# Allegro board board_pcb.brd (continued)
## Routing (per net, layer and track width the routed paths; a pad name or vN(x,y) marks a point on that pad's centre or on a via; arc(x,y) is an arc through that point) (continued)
LCD_G1: length 121.1
  TOP w0.152: J1.14 113.1,102.62 117.02,98.7 117.02,97.94 117.53,97.43 117.53,97 117.81,96.72 117.81,96.5 117.62,96.31 117.62,96.1 117.84,95.88 118.05,95.88 118.24,96.07 118.46,96.07 118.87,95.66 119.2,95.66 119.74,96.19 120.22,96.19 120.52,95.89 120.52,94.72 120.29,94.49 J2.14 ; U1.N13 v2(55.67,66.85)
  BOTTOM w0.152: J2.14 119,92.93 119.15,92.77 119.48,92.77 119.63,92.62 119.63,92.32 119.48,92.16 119.15,92.16 119,92.01 119,91.71 119.15,91.55 119.48,91.55 119.63,91.4 119.63,91.1 119.48,90.94 119.15,90.94 119,90.79 119,90.04 118.85,89.89 118.4,89.89 118.25,90.04 118.25,92.68 118.1,92.84 117.79,92.84 117.64,92.68 117.64,90.04 117.49,89.89 117.18,89.89 117.03,90.04 117.03,92.02 116.88,92.18 116.57,92.18 116.42,92.02 116.42,90.04 116.27,89.89 115.96,89.89 115.81,90.04 115.81,91.01 115.66,91.16 115.35,91.16 115.2,91.01 115.2,90.04 114.43,89.27 92.09,89.27 90.04,87.22 90.04,86.45 89.89,86.3 89.31,86.3 89.15,86.15 89.15,85.85 89.31,85.69 89.89,85.69 90.04,85.54 90.04,84.71 89.75,84.42 89.54,84.42 88.67,85.28 88.46,85.28 88.24,85.07 88.24,84.85 89.11,83.99 89.11,83.77 88.89,83.56 88.67,83.56 87.81,84.42 87.6,84.42 87.38,84.2 87.38,83.99 88.24,83.12 88.24,82.91 87.76,82.42 86.87,82.42 86.11,81.66 86.11,80.64 85.93,80.47 85.71,80.47 85.48,80.7 85.27,80.7 85.05,80.48 85.05,80.26 85.28,80.03 85.28,79.82 85.06,79.6 84.85,79.6 84.62,79.83 84.4,79.83 84.19,79.62 84.19,79.4 84.42,79.17 84.42,78.96 84.2,78.74 83.99,78.74 83.76,78.97 83.54,78.97 83.33,78.75 83.33,78.54 83.56,78.31 83.56,78.09 80.61,75.14 62.44,75.14 61.49,74.19 61.49,72.75 60.96,72.21 59.26,72.21 57.66,70.61 57.66,70.23 56.07,68.64 56.07,67.25 v2(55.67,66.85)
LCD_G2: length 121.3
  TOP w0.152: U1.M14 v2(54.87,67.65) ; 116.46,97.03 115.54,97.03 115.39,97.18 115.39,97.64 115.82,98.07 116.51,98.07 116.66,98.22 116.66,98.55 116.18,99.04 115.96,99.04 115.54,98.62 115.33,98.62 115.11,98.83 115.11,99.05 115.53,99.47 115.53,99.68 115.31,99.9 115.1,99.9 114.68,99.48 114.46,99.48 114.25,99.7 114.25,99.91 114.67,100.33 114.67,100.55 114.45,100.76 114.24,100.76 113.82,100.34 113.6,100.34 113.39,100.56 113.39,100.78 113.8,101.19 113.8,101.41 113.59,101.63 113.37,101.63 112.95,101.21 112.74,101.21 112.52,101.42 112.52,101.64 112.94,102.06 112.94,102.27 112.61,102.61 J1.15
  BOTTOM w0.152: v2(54.87,67.65) U1.M14 53.82,67.25 53.67,67.4 53.67,68.71 53.11,69.27 53.11,70.38 52.02,71.48 52.02,73.2 55.27,76.45 58.42,76.45 58.8,76.83 73.86,76.83 74.28,77.25 74.28,77.47 73.51,78.24 73.51,78.46 73.72,78.68 73.94,78.68 74.71,77.9 74.93,77.9 75.15,78.12 75.15,78.33 74.37,79.11 74.37,79.32 74.59,79.54 74.8,79.54 75.58,78.76 75.79,78.76 76.01,78.98 76.01,79.2 75.23,79.97 75.23,80.19 75.45,80.4 75.66,80.4 76.44,79.63 76.65,79.63 76.87,79.84 76.87,80.06 76.1,80.83 76.1,81.05 76.31,81.26 76.53,81.26 77.3,80.49 77.52,80.49 77.73,80.7 77.73,80.92 76.96,81.7 76.96,81.91 77.17,82.13 77.39,82.13 78.16,81.35 78.38,81.35 78.59,81.56 78.59,81.86 78.36,82.09 78.36,82.4 78.73,82.77 78.73,82.98 78.5,83.21 78.5,83.43 78.72,83.64 78.93,83.64 79.16,83.41 79.38,83.41 79.59,83.63 79.59,83.84 79.36,84.07 79.36,84.29 79.58,84.51 79.79,84.51 80.02,84.28 80.24,84.28 80.45,84.49 80.45,84.71 80.22,84.94 80.22,85.15 80.44,85.37 80.66,85.37 80.88,85.14 81.1,85.14 81.32,85.35 81.32,85.57 81.09,85.8 81.09,86.01 81.3,86.23 81.52,86.23 81.75,86 81.96,86 82.18,86.22 82.18,86.43 81.95,86.66 81.95,86.88 82.17,87.09 82.38,87.09 82.61,86.86 82.83,86.86 83.07,87.11 83.07,87.33 82.7,87.7 82.7,87.91 82.92,88.13 83.13,88.13 83.5,87.76 83.72,87.76 83.94,87.97 83.94,88.19 83.57,88.56 83.57,88.77 83.78,88.99 84,88.99 84.37,88.62 84.58,88.62 84.8,88.84 84.8,89.05 84.43,89.42 84.43,89.64 84.64,89.85 84.86,89.85 85.23,89.48 85.44,89.48 86.87,90.91 112.19,90.91 115.32,94.03 115.32,95.89 116.46,97.03
LCD_G3: length 121.2
  TOP w0.152: U1.L14 v2(54.07,67.65) ; 116.46,94.49 116.92,94.03 117.7,94.03 117.86,94.18 117.86,95.33 117.65,95.53 117.27,95.53 117.11,95.68 117.11,95.83 116.96,95.99 116.66,95.99 116.51,95.83 116.51,95.68 116.35,95.53 115.9,95.53 115.77,95.66 115.77,95.87 115.84,95.94 115.84,96.15 115.62,96.37 115.4,96.37 115.34,96.31 115.12,96.31 114.96,96.47 114.96,97.74 115.21,97.99 115.21,98.22 112.17,101.27 112.17,101.8 112.41,102.05 112.41,102.27 112.1,102.58 J1.16
  BOTTOM w0.152: 116.46,94.49 112.48,90.51 89.56,90.51 87.93,88.88 87.72,88.88 86.82,89.78 86.61,89.78 86.39,89.56 86.39,89.35 87.29,88.45 87.29,88.24 87.07,88.02 86.85,88.02 85.96,88.92 85.74,88.92 85.53,88.7 85.53,88.49 86.42,87.59 86.42,87.37 86.21,87.16 85.99,87.16 85.1,88.05 84.88,88.05 84.66,87.84 84.66,87.62 85.56,86.73 85.56,86.51 85.34,86.3 85.13,86.3 84.23,87.19 84.02,87.19 83.8,86.98 83.8,86.76 84.7,85.86 84.7,85.65 84.48,85.43 84.27,85.43 83.37,86.33 83.16,86.33 82.94,86.11 82.94,85.9 83.84,85 83.84,84.79 83.62,84.57 83.4,84.57 82.51,85.47 82.29,85.47 82.08,85.25 82.08,85.04 82.97,84.14 82.97,83.92 82.76,83.71 82.54,83.71 81.65,84.6 81.43,84.6 81.21,84.39 81.21,84.17 82.11,83.28 82.11,83.06 81.89,82.85 81.68,82.85 80.78,83.74 80.57,83.74 80.35,83.53 80.35,83.31 81.25,82.41 81.25,82.2 81.03,81.98 80.82,81.98 79.92,82.88 79.7,82.88 79.49,82.66 79.49,82.45 80.39,81.55 80.39,81.34 80.14,81.09 79.78,81.09 79.46,81.41 79.25,81.41 74.22,76.38 58.98,76.38 58.55,75.95 55.35,75.95 52.45,73.05 52.45,71.63 53.53,70.55 53.53,69.65 54.47,68.71 54.47,68.05 v2(54.07,67.65)
LCD_G4: length 121.4
  TOP w0.152: J2.17 113.92,96.19 113.77,96.04 113.03,96.04 112.84,96.23 112.84,97.9 113,98.07 114.29,98.07 114.44,98.22 114.44,98.44 113.56,99.32 113.34,99.32 112.74,98.72 112.53,98.72 112.31,98.94 112.31,99.15 112.91,99.75 112.91,99.97 112.69,100.18 112.48,100.18 111.91,99.61 111.69,99.61 111.48,99.83 111.48,100.04 112.05,100.61 112.05,100.83 111.61,101.27 111.61,101.7 111.76,101.86 111.76,102.49 111.61,102.64 J1.17 ; U1.K14 v2(53.27,67.65)
  BOTTOM w0.152: J2.17 113.92,96.01 112.78,94.87 112.78,94.03 110.44,91.69 82.88,91.69 82.3,91.11 82.08,91.11 81.58,91.62 81.36,91.62 81.14,91.41 81.14,91.19 81.65,90.68 81.65,90.47 81.44,90.25 81.22,90.25 80.71,90.76 80.5,90.76 80.28,90.54 80.28,90.33 80.79,89.82 80.79,89.6 80.57,89.39 80.36,89.39 79.85,89.9 79.64,89.9 79.42,89.68 79.42,89.47 79.93,88.96 79.93,88.74 79.67,88.48 79.67,88.27 79.99,87.95 79.99,87.73 79.77,87.52 79.56,87.52 79.24,87.84 79.02,87.84 78.81,87.62 78.81,87.4 79.12,87.09 79.12,86.87 78.91,86.65 78.69,86.65 78.37,86.97 78.16,86.97 77.94,86.76 77.94,86.54 78.26,86.22 78.26,86.01 78.05,85.79 77.83,85.79 77.51,86.11 77.3,86.11 77.08,85.89 77.08,85.68 77.4,85.36 77.4,85.15 77.18,84.93 76.97,84.93 76.65,85.25 76.43,85.25 76.22,85.03 76.22,84.82 76.54,84.5 76.54,84.28 76.32,84.07 76.1,84.07 75.79,84.39 75.57,84.39 75.36,84.17 75.36,83.95 75.67,83.64 75.67,83.42 75.46,83.2 75.24,83.2 74.92,83.52 74.71,83.52 74.49,83.31 74.49,83.09 74.81,82.77 74.81,82.56 74.59,82.34 74.38,82.34 74.06,82.66 73.85,82.66 73.63,82.44 73.63,82.23 73.95,81.91 73.95,81.7 73.73,81.48 73.52,81.48 73.2,81.8 72.98,81.8 72.77,81.58 72.77,81.37 73.09,81.05 73.09,80.83 72.87,80.62 72.65,80.62 72.34,80.93 72.12,80.93 71.91,80.72 71.91,80.5 72.22,80.19 72.22,79.97 72.01,79.75 71.79,79.75 71.47,80.07 71.26,80.07 71.04,79.86 71.04,79.64 71.36,79.32 71.36,79.11 71.14,78.89 70.93,78.89 70.61,79.21 70.4,79.21 70.31,79.12 70.1,79.12 69.49,78.51 69.49,78 69.22,77.72 68.69,77.72 68.54,77.88 68.54,79.02 68.39,79.17 68.08,79.17 67.93,79.02 67.93,77.81 67.78,77.66 67.29,77.66 67.13,77.81 67.13,78.23 66.98,78.38 66.68,78.38 66.52,78.23 66.52,77.81 66.37,77.66 66.07,77.66 65.91,77.81 65.91,78.23 65.76,78.38 65.46,78.38 65.3,78.23 65.3,77.88 65.15,77.72 58.42,77.72 58.01,77.32 53.95,77.32 51.13,74.5 51.13,71.04 51.68,70.49 51.68,69.01 52.07,68.62 52.07,67.46 52.29,67.25 U1.K14 v2(53.27,67.65)
LCD_G5: length 121.3
  TOP w0.152: J1.18 111.1,102.84 111.23,102.72 111.23,100.3 111.1,100.18 111.1,99.62 112.42,98.3 112.42,95.33 112.57,95.17 113.08,95.17 113.49,95.58 114.2,95.58 114.35,95.73 114.35,95.96 114.5,96.11 114.81,96.11 114.96,95.96 114.96,95.73 115.11,95.58 115.24,95.58 115.39,95.43 115.39,94.13 115.24,93.98 114.43,93.98 J2.18 ; U1.J14 v2(52.47,67.65)
  BOTTOM w0.152: v2(52.47,67.65) 52.81,67.98 52.81,68.33 52.03,69.11 52.03,70.83 51.59,71.27 51.59,73.43 51.83,73.67 51.83,73.89 51.61,74.1 51.61,74.32 51.83,74.53 52.04,74.53 52.26,74.32 52.47,74.32 52.69,74.53 52.69,74.75 52.47,74.97 52.47,75.18 52.69,75.4 52.9,75.4 53.12,75.18 53.34,75.18 54.99,76.83 58.17,76.83 58.55,77.22 70.12,77.22 70.28,77.37 70.28,78.33 70.43,78.49 70.73,78.49 70.89,78.33 70.89,77.37 71.04,77.22 71.34,77.22 71.5,77.37 71.5,78.46 71.65,78.61 71.95,78.61 72.1,78.46 72.1,77.37 72.26,77.22 72.62,77.22 72.77,77.37 72.77,79.88 73.56,80.67 73.77,80.67 74.23,80.21 74.45,80.21 74.66,80.43 74.66,80.64 74.2,81.1 74.2,81.32 74.42,81.53 74.64,81.53 75.09,81.07 75.31,81.07 75.52,81.29 75.52,81.51 75.07,81.96 75.07,82.18 75.28,82.39 75.5,82.39 75.96,81.94 76.17,81.94 76.39,82.15 76.39,82.37 75.93,82.83 75.93,83.04 76.15,83.26 76.36,83.26 76.82,82.8 77.03,82.8 77.25,83.02 77.25,83.23 76.79,83.69 76.79,83.9 77.01,84.12 77.22,84.12 77.68,83.66 77.9,83.66 78.11,83.88 78.11,84.09 77.65,84.55 77.65,84.77 77.87,84.98 78.09,84.98 78.54,84.52 78.76,84.52 78.97,84.74 78.97,84.96 78.52,85.41 78.52,85.63 78.73,85.84 78.95,85.84 79.41,85.39 79.62,85.39 79.84,85.6 79.84,85.82 79.38,86.28 79.38,86.49 79.6,86.71 79.81,86.71 80.27,86.25 80.48,86.25 80.7,86.47 80.7,86.68 80.24,87.14 80.24,87.35 80.46,87.57 80.67,87.57 81.13,87.11 81.35,87.11 81.56,87.33 81.56,87.54 81.1,88 81.1,88.22 81.43,88.54 81.43,88.76 81.13,89.06 81.13,89.28 81.34,89.49 81.56,89.49 81.86,89.19 82.08,89.19 82.29,89.41 82.29,89.62 81.99,89.93 81.99,90.14 82.2,90.36 82.42,90.36 82.72,90.05 82.94,90.05 83.16,90.27 83.16,90.48 82.85,90.79 82.85,91 83.07,91.22 83.28,91.22 83.59,90.91 83.8,90.91 84.2,91.31 112.01,91.31 112.78,92.08 112.78,92.3 112.38,92.7 112.38,92.92 112.59,93.14 112.81,93.14 113.21,92.73 113.43,92.73 113.92,93.22 J2.18
LCD_G6: length 121.1
  TOP w0.152: 111.38,97.03 111.38,95.68 111.23,95.53 110.49,95.53 110.34,95.68 110.34,97.92 110.49,98.07 111.58,98.07 111.73,98.22 111.73,98.48 111.51,98.7 110.87,98.7 110.72,98.86 110.72,99.17 110.57,99.33 109.5,99.33 109.35,99.48 109.35,99.78 109.5,99.94 110.57,99.94 110.72,100.09 110.72,100.33 110.82,100.43 110.82,100.78 110.67,100.93 110.31,100.93 110.16,101.08 110.16,101.39 110.31,101.54 110.67,101.54 110.82,101.69 110.82,102.57 110.61,102.78 J1.19 ; U1.J15 v2(51.67,68.45)
  BOTTOM w0.152: 111.38,97.03 110.39,97.03 110.24,96.88 110.24,96.3 110.08,96.15 109.7,96.15 109.55,96 109.55,95.69 109.7,95.54 110.08,95.54 110.24,95.39 110.24,94.23 108.74,92.74 107.91,92.74 107.76,92.89 107.76,93.29 107.61,93.45 107.3,93.45 107.15,93.29 107.15,92.89 107,92.74 106.69,92.74 106.54,92.89 106.54,93.29 106.39,93.45 106.08,93.45 105.93,93.29 105.93,92.89 105.78,92.74 105.48,92.74 105.32,92.89 105.32,93.29 105.17,93.45 104.87,93.45 104.71,93.29 104.71,92.89 104.56,92.74 104.26,92.74 104.1,92.89 104.1,93.29 103.95,93.45 103.65,93.45 103.49,93.29 103.49,92.89 103.34,92.74 103.04,92.74 102.88,92.89 102.88,93.29 102.73,93.45 102.43,93.45 102.27,93.29 102.27,92.89 102.12,92.74 101.82,92.74 101.67,92.89 101.67,93.29 101.51,93.45 101.21,93.45 101.06,93.29 101.06,92.89 100.9,92.74 100.6,92.74 100.45,92.89 100.45,93.29 100.29,93.45 99.99,93.45 99.84,93.29 99.84,92.89 99.68,92.74 99.38,92.74 99.23,92.89 99.23,93.29 99.07,93.45 98.77,93.45 98.62,93.29 98.62,92.89 98.46,92.74 98.16,92.74 98.01,92.89 98.01,93.29 97.86,93.45 97.55,93.45 97.4,93.29 97.4,92.89 97.02,92.51 80.82,92.51 78.94,90.63 77.19,90.63 76.57,90.01 76.57,89.79 76.92,89.45 76.92,89.23 76.7,89.02 76.48,89.02 76.14,89.36 75.93,89.36 75.71,89.15 75.71,88.93 76.05,88.59 76.05,88.37 75.84,88.16 75.62,88.16 75.28,88.5 75.06,88.5 74.85,88.28 74.85,88.07 75.19,87.72 75.19,87.51 74.97,87.29 74.76,87.29 74.42,87.64 74.2,87.64 73.98,87.42 73.98,87.21 74.33,86.86 74.33,86.65 74.11,86.43 73.9,86.43 73.55,86.77 73.34,86.77 73.12,86.56 73.12,86.34 73.47,86 73.47,85.78 73.25,85.57 73.03,85.57 72.69,85.91 72.48,85.91 72.26,85.7 72.26,85.48 72.6,85.14 72.6,84.92 72.39,84.71 72.17,84.71 71.83,85.05 71.61,85.05 71.4,84.83 71.4,84.62 71.74,84.27 71.74,84.06 71.52,83.84 71.31,83.84 70.97,84.19 70.75,84.19 70.53,83.97 70.53,83.76 70.88,83.41 70.88,83.2 70.66,82.98 70.45,82.98 70.1,83.32 69.89,83.32 69.67,83.11 69.67,82.89 70.01,82.55 70.01,82.33 69.8,82.12 69.58,82.12 69.24,82.46 69.02,82.46 68.81,82.25 68.81,82.03 69.15,81.69 69.15,81.47 68.94,81.26 68.72,81.26 68.38,81.6 68.16,81.6 67.92,81.36 67.92,80.57 66.65,79.3 64.89,79.3 64.26,78.67 63.91,78.67 63.75,78.82 63.75,79.4 63.6,79.55 63.3,79.55 63.14,79.4 63.14,78.82 62.99,78.67 58.1,78.67 57.51,78.08 53.42,78.08 49.4,74.07 49.4,71.63 50.42,70.61 50.93,70.61 51.32,70.22 51.32,68.79 v2(51.67,68.45)
LCD_G7: length 121.4
  TOP w0.152: J1.20 110.1,102.77 110.36,102.51 110.36,102.11 109.8,101.55 109.8,100.71 109.65,100.56 109.14,100.56 108.99,100.41 108.99,99.31 109.35,98.96 110.09,98.96 110.3,98.75 110.3,98.41 109.75,97.87 109.75,97.56 109.98,97.33 109.98,96.23 109.83,96.08 109.35,96.08 109.19,95.93 109.19,95.62 109.35,95.47 109.83,95.47 109.98,95.32 109.98,93.6 110.13,93.45 111.23,93.45 111.38,93.6 111.38,94.49 ; U1.H17 51.27,71.65 50.69,72.24 v2(50.69,72.26)
  BOTTOM w0.152: 111.38,94.49 111.38,93.55 111.07,93.24 110.85,93.24 110.48,93.6 110.27,93.6 110.05,93.39 110.05,93.17 110.42,92.8 110.42,92.59 109.93,92.1 81.05,92.1 79.06,90.11 78.55,90.11 78.3,89.85 78.3,89.64 79.07,88.86 79.07,88.65 78.86,88.43 78.64,88.43 77.87,89.21 77.65,89.21 77.43,88.99 77.43,88.78 78.21,88 78.21,87.79 77.99,87.57 77.78,87.57 77,88.34 76.79,88.34 76.57,88.13 76.57,87.91 77.35,87.14 77.35,86.92 77.13,86.71 76.92,86.71 76.14,87.48 75.92,87.48 75.71,87.27 75.71,87.05 76.48,86.28 76.48,86.06 76.27,85.84 76.05,85.84 75.28,86.62 75.06,86.62 74.85,86.4 74.85,86.19 75.62,85.41 75.62,85.2 75.41,84.98 75.19,84.98 74.42,85.76 74.2,85.76 73.98,85.54 73.98,85.33 74.76,84.55 74.76,84.33 74.54,84.12 74.33,84.12 73.55,84.89 73.34,84.89 73.12,84.68 73.12,84.46 73.9,83.69 73.9,83.47 73.68,83.26 73.47,83.26 72.69,84.03 72.47,84.03 72.26,83.82 72.26,83.6 73.03,82.83 73.03,82.61 72.82,82.39 72.6,82.39 71.83,83.17 71.61,83.17 71.4,82.95 71.4,82.74 72.17,81.96 72.17,81.75 71.96,81.53 71.74,81.53 70.96,82.31 70.75,82.31 70.53,82.09 70.53,81.88 71.31,81.1 71.31,80.88 71.09,80.67 70.88,80.67 70.1,81.44 69.89,81.44 69.67,81.23 69.67,81.01 70.45,80.24 70.45,80.02 70.23,79.81 70.01,79.81 69.24,80.58 69.02,80.58 68.81,80.37 68.81,80.15 69.58,79.37 69.58,79.16 69.37,78.94 69.15,78.94 68.38,79.72 68.16,79.72 68.15,79.71 67.64,79.71 66.78,78.84 65.14,78.84 64.53,78.23 58.17,78.23 57.63,77.7 53.68,77.7 50.66,74.68 50.66,72.29 v2(50.69,72.26)
LCD_HSYNC: length 121.5
  TOP w0.152: J2.32 95.1,95.53 95.1,97.75 96.77,99.42 97.41,99.42 97.56,99.58 97.56,99.8 97.71,99.95 101.22,99.95 104.1,102.83 J1.32 ; U1.H1 v2(50.87,56.45)
  ART03 w0.114: v1(64.39,80.64) 63.67,80.64 61.05,83.26 51.51,83.26 50.16,81.92 46.48,81.92 45.85,81.28 44.58,81.28 43.43,80.14 43.43,79.38 39.02,74.96 39.02,64.52 40.15,63.39 40.15,61.61 41.72,60.04 41.72,59.37 45.21,55.88 50.3,55.88 v2(50.87,56.45)
  BOTTOM w0.152: J2.32 95.25,94.49 94.18,93.42 85.02,93.42 84.84,93.6 84.84,94.56 84.69,94.72 84.38,94.72 84.23,94.56 84.23,93.6 84.08,93.45 83.77,93.45 83.62,93.6 83.62,94.56 83.47,94.72 83.16,94.72 83.01,94.56 83.01,93.6 82.86,93.45 82.55,93.45 82.4,93.6 82.4,94.56 82.25,94.72 81.94,94.72 81.79,94.56 81.79,93.6 81.64,93.45 81.33,93.45 81.18,93.6 81.18,94.56 81.03,94.72 80.72,94.72 80.57,94.56 80.57,93.6 80.42,93.45 80.32,93.45 78.44,91.57 76.58,91.57 66.17,81.15 66.17,80.24 65.94,80.01 65.02,80.01 v1(64.39,80.64)
LCD_PWM: length 122.1
  TOP w0.152: J1.35 102.61,102.94 101.13,101.46 97.32,101.46 97.16,101.3 95.33,101.3 94.05,100.02 93.83,100.02 93.72,100.13 93.5,100.13 93.28,99.91 93.28,99.7 93.4,99.58 93.4,99.37 93.18,99.15 92.97,99.15 92.85,99.27 92.64,99.27 92.42,99.05 92.42,98.84 92.54,98.72 92.54,98.51 J2.35 ; U1.E15 v2(48.47,68.45)
  BOTTOM w0.152: v2(48.47,68.45) 48.29,68.45 48.13,68.6 48.13,69.72 48.9,70.48 48.9,72.3 48.74,72.45 44.55,72.45 44.4,72.61 44.4,72.91 44.55,73.06 48.74,73.06 48.9,73.22 48.9,73.7 48.74,73.86 48.18,73.86 48.03,74.01 48.03,74.31 48.18,74.47 49.14,74.47 50.63,75.95 50.63,76.17 50.13,76.66 50.13,76.88 50.35,77.1 50.57,77.1 51.06,76.6 51.28,76.6 51.49,76.82 51.49,77.03 51,77.53 51,77.74 51.21,77.96 51.43,77.96 51.92,77.46 52.14,77.46 53.26,78.59 55.47,78.59 56.52,79.63 61.9,79.63 63.93,81.66 64.77,81.66 67.58,84.48 67.58,84.69 67.02,85.25 67.02,85.47 67.24,85.68 67.46,85.68 68.02,85.12 68.23,85.12 68.45,85.34 68.45,85.55 67.89,86.11 67.89,86.33 68.1,86.54 68.32,86.54 68.88,85.98 69.09,85.98 69.31,86.2 69.31,86.42 68.75,86.97 68.75,87.19 68.97,87.41 69.18,87.41 69.74,86.85 69.96,86.85 70.17,87.06 70.17,87.28 69.61,87.84 69.61,88.05 69.83,88.27 70.04,88.27 70.6,87.71 70.82,87.71 71.03,87.93 71.03,88.14 70.48,88.7 70.48,88.92 70.69,89.13 70.91,89.13 71.47,88.57 71.68,88.57 71.9,88.79 71.9,89 71.34,89.56 71.34,89.78 71.55,89.99 71.77,89.99 72.33,89.43 72.54,89.43 72.76,89.65 72.76,89.87 72.2,90.43 72.2,90.64 72.42,90.86 72.63,90.86 73.19,90.3 73.41,90.3 73.62,90.51 73.62,90.73 73.06,91.29 73.06,91.5 73.28,91.72 73.49,91.72 74.05,91.16 74.27,91.16 74.48,91.38 74.48,91.59 73.93,92.15 73.93,92.37 74.14,92.58 74.36,92.58 74.92,92.02 75.13,92.02 75.35,92.24 75.35,92.45 74.79,93.01 74.79,93.23 75,93.44 75.22,93.44 75.78,92.89 75.99,92.89 76.21,93.1 76.21,93.32 75.65,93.88 75.65,94.09 75.87,94.31 76.08,94.31 76.64,93.75 76.86,93.75 77.07,93.96 77.07,94.18 76.51,94.74 76.51,94.95 76.73,95.17 76.94,95.17 77.5,94.61 77.72,94.61 77.94,94.83 77.94,95.04 77.38,95.6 77.38,95.82 77.59,96.03 77.81,96.03 78.37,95.47 78.58,95.47 78.8,95.69 78.8,95.9 78.24,96.46 78.24,96.68 78.45,96.89 78.67,96.89 79.23,96.34 79.44,96.34 79.66,96.55 79.66,96.77 79.1,97.33 79.1,97.54 79.32,97.76 79.53,97.76 80.09,97.2 80.31,97.2 81.2,98.09 81.59,98.09 81.74,97.94 81.74,97.64 81.9,97.49 82.2,97.49 82.35,97.64 82.35,97.94 82.51,98.09 82.81,98.09 82.96,97.94 82.96,97.64 83.11,97.49 83.42,97.49 83.57,97.64 83.57,97.94 83.72,98.09 84.03,98.09 84.18,97.94 84.18,97.64 84.33,97.49 84.64,97.49 84.79,97.64 84.79,97.94 84.94,98.09 87.43,98.09 87.91,98.58 89.26,98.58 89.42,98.42 89.42,97.59 89.57,97.43 89.87,97.43 90.03,97.59 90.03,98.42 90.18,98.58 90.91,98.58 91.06,98.42 J2.35
LCD_R0: length 118.9
  TOP w0.152: U1.P5 v2(56.47,59.65) ; J2.5 129.16,97.66 127.83,98.99 127.62,98.99 127.54,98.91 127.32,98.91 127.11,99.13 127.11,99.35 127.18,99.42 127.18,99.64 126.97,99.85 126.75,99.85 126.68,99.78 126.46,99.78 126.24,99.99 126.24,100.21 126.32,100.29 126.32,100.5 126.11,100.72 125.89,100.72 125.81,100.64 125.6,100.64 123.55,102.69 117.88,102.69 117.61,102.97 J1.5 ; v1(63.75,73.79) 63.14,73.18 62.13,73.18 61.49,72.54 61.49,67.46 60.33,66.29 60.33,62.19 v2(60.79,61.72)
  BOTTOM w0.152: v2(56.47,59.65) 56.87,59.25 58.87,59.25 60.79,61.18 v2(60.79,61.72) ; v1(63.75,73.79) 81.41,73.79 91.69,84.07 91.69,86.61 93.12,88.04 122.71,88.04 123.05,88.38 123.27,88.38 123.43,88.21 123.65,88.21 123.86,88.43 123.86,88.65 123.7,88.81 123.7,89.03 123.91,89.24 124.13,89.24 124.29,89.08 124.51,89.08 124.73,89.29 124.73,89.51 124.56,89.67 124.56,89.89 125.55,90.88 125.55,92.42 125.7,92.57 126.42,92.57 126.57,92.72 126.57,93.03 126.42,93.18 125.7,93.18 125.55,93.33 125.55,95.22 126.06,95.73 127.86,95.73 J2.5
LCD_R1: length 118.9
  TOP w0.152: J2.6 127.82,96.99 127.69,97.3 127.38,97.77 126.85,98.29 123.87,100.74 121.62,102.24 121.4,102.34 117.79,102.34 117.64,102.4 117.1,102.94 J1.6 ; v2(60.83,62.74) 60.83,63.91 60.99,64.06 61.19,64.06 61.34,64.22 61.34,64.52 61.19,64.67 60.99,64.67 60.83,64.83 60.83,65.18 61.98,66.32 61.98,72.01 v1(62.61,72.64) ; U1.N6 v2(55.67,60.45)
  BOTTOM w0.152: J2.6 126.22,91.55 126.22,90.62 126.43,90.4 126.43,90.19 126.22,89.97 126,89.97 125.78,90.19 125.57,90.19 125.35,89.97 125.35,89.76 125.57,89.54 125.57,89.32 123.88,87.63 93.73,87.63 92.33,86.23 92.33,83.31 91.96,82.94 91.75,82.94 91.71,82.98 91.49,82.98 91.28,82.77 91.28,82.55 91.31,82.51 91.31,82.3 91.1,82.08 90.88,82.08 90.84,82.12 90.63,82.12 90.41,81.9 90.41,81.69 90.45,81.65 90.45,81.43 90.24,81.22 90.02,81.22 89.98,81.26 89.77,81.26 89.55,81.04 89.55,80.83 89.59,80.79 89.59,80.57 89.37,80.36 89.16,80.36 89.12,80.39 88.9,80.39 88.69,80.18 88.69,79.96 88.73,79.92 88.73,79.71 88.51,79.49 88.3,79.49 88.26,79.53 88.04,79.53 87.83,79.32 87.83,79.1 87.86,79.06 87.86,78.85 87.65,78.63 87.43,78.63 87.39,78.67 87.18,78.67 86.96,78.45 86.96,78.24 87,78.2 87,77.98 86.79,77.77 86.57,77.77 86.53,77.81 86.32,77.81 86.1,77.59 86.1,77.38 86.14,77.34 86.14,77.12 85.92,76.91 85.71,76.91 85.67,76.94 85.45,76.94 85.24,76.73 85.24,76.51 85.28,76.47 85.28,76.26 85.06,76.04 84.84,76.04 84.81,76.08 84.59,76.08 84.37,75.87 84.37,75.65 84.41,75.61 84.41,75.4 84.2,75.18 83.98,75.18 83.94,75.22 83.73,75.22 83.51,75 83.51,74.79 83.55,74.75 83.55,74.53 83.34,74.32 83.12,74.32 83.08,74.36 82.87,74.36 82.65,74.14 82.65,73.93 82.69,73.89 82.69,73.67 82.25,73.23 63.2,73.23 v1(62.61,72.64) ; v2(60.83,62.74) 60.33,62.23 60.33,61.47 58.5,59.65 57.04,59.65 56.64,60.05 56.07,60.05 v2(55.67,60.45)
LCD_R2: length 118.5
  TOP w0.152: U1.P6 v2(56.47,60.45) ; v2(59.82,61.72) 59.82,66.67 61.01,67.87 61.01,72.87 61.93,73.79 v1(62.61,73.79) ; J2.7 126.62,97.89 126.47,98.04 125.25,98.04 124.86,98.43 124.86,98.65 125.15,98.94 125.15,99.15 124.94,99.37 124.72,99.37 124.43,99.08 124.21,99.08 124,99.29 124,99.51 124.22,99.72 124.22,99.94 124,100.16 123.78,100.16 123.57,99.94 123.35,99.94 122.84,100.45 122.84,100.67 122.85,100.68 122.85,100.9 122.64,101.11 122.42,101.11 122.41,101.1 122.19,101.1 121.31,101.98 117.55,101.98 116.61,102.93 J1.7
  BOTTOM w0.152: v2(59.82,61.72) 58.1,60 57.12,60 56.67,60.45 v2(56.47,60.45) ; v1(62.61,73.79) 63.17,74.35 81.2,74.35 91.14,84.28 91.14,86.92 92.67,88.45 122.49,88.45 123.95,89.91 123.95,90.12 123.65,90.42 123.65,90.63 123.87,90.85 124.08,90.85 124.38,90.56 124.59,90.56 125.12,91.08 125.12,91.37 124.97,91.52 123.77,91.52 123.62,91.68 123.62,91.98 123.77,92.13 124.97,92.13 125.12,92.29 125.12,92.59 124.97,92.74 123.77,92.74 123.62,92.9 123.62,93.2 123.77,93.35 124.97,93.35 125.12,93.51 125.12,95.53 J2.7
LCD_R3: length 121.7
  TOP w0.152: J1.8 116.1,102.89 117.37,101.63 121.16,101.63 125.15,97.64 125.15,96.32 125.7,95.76 126.47,95.76 126.62,95.61 J2.8 ; U1.T6 58.07,60.45 61.21,60.45 64.39,63.63 64.39,72.01 v1(63.75,72.64)
  BOTTOM w0.152: v1(63.75,72.64) 82.42,72.64 93.47,83.69 93.47,84.12 93.32,84.27 93.12,84.27 92.96,84.42 92.96,84.73 93.12,84.88 93.32,84.88 93.47,85.03 93.47,85.33 93.32,85.49 93.12,85.49 92.96,85.64 92.96,85.94 93.12,86.1 93.32,86.1 93.47,86.25 93.47,86.61 94.01,87.15 124.1,87.15 127.4,90.44 127.4,90.66 127.06,91 127.06,91.22 127.27,91.43 127.49,91.43 127.83,91.09 128.05,91.09 128.26,91.31 128.26,91.52 127.92,91.86 127.92,92.08 128.14,92.3 128.35,92.3 128.69,91.95 128.91,91.95 129.13,92.17 129.13,92.38 128.78,92.73 128.78,92.94 129,93.16 129.21,93.16 129.56,92.81 129.77,92.81 130.2,93.24 130.2,95.45 130.02,95.63 128.55,95.63 127.41,94.49 J2.8
LCD_R4: length 122.3
  TOP w0.152: J2.9 124.08,98.2 123.76,98.51 123.55,98.51 123.22,98.18 123,98.18 122.78,98.4 122.78,98.61 123.12,98.94 123.12,99.16 122.9,99.38 122.68,99.38 122.35,99.05 122.14,99.05 121.92,99.26 121.92,99.48 122.25,99.81 122.25,100.02 122.04,100.24 121.82,100.24 121.49,99.91 121.28,99.91 121.06,100.12 121.06,100.34 121.39,100.67 121.39,100.89 121.01,101.27 117.22,101.27 115.61,102.89 J1.9 ; v1(63.75,71.5) 63.75,65.38 arc(63.41,63.64) 62.43,62.17 61.1,60.85 U1.U6
  BOTTOM w0.152: J2.9 124.61,97.56 125.78,98.34 126.17,98.5 130.21,98.5 132.35,98.07 132.5,97.93 132.82,97.16 132.82,94.54 132.71,94 124.99,86.28 96.32,86.28 94.87,84.84 94.87,83.31 83.19,71.63 63.88,71.63 v1(63.75,71.5)
LCD_R5: length 121.9
  TOP w0.152: J1.10 115.1,102.88 117.07,100.91 120.54,100.91 120.65,100.81 120.65,100.03 123.04,97.64 123.04,96.55 123.88,95.71 124.49,95.71 124.97,95.22 124.97,94.87 124.59,94.49 J2.10 ; v1(62.61,71.5) 62.61,63.65 61.44,62.48 61.44,61.7 60.97,61.22 58.9,61.22 U1.U7
  BOTTOM w0.152: J2.10 124.08,95.33 125.35,96.6 125.35,97.28 126.14,98.07 129.67,98.07 130.56,97.18 130.56,92.89 124.41,86.74 94.61,86.74 94.23,86.36 94.23,83.57 82.75,72.09 63.2,72.09 v1(62.61,71.5)
LCD_R6: length 121.2
  TOP w0.152: U1.R12 v2(57.27,66.05) ; J1.11 114.61,102.87 116.92,100.56 117.39,100.56 117.54,100.41 117.54,99.8 117.7,99.64 118,99.64 118.15,99.8 118.15,100.41 118.31,100.56 118.61,100.56 118.76,100.41 118.76,99.77 118.92,99.62 119.22,99.62 119.37,99.77 119.37,100.41 119.53,100.56 120.14,100.56 120.29,100.41 120.29,99.85 122.68,97.47 122.68,97.18 122.52,97.03 121.54,97.03
  BOTTOM w0.152: v2(57.27,66.05) 56.87,66.45 56.87,68.68 57.83,69.65 58.32,69.65 58.47,69.8 58.47,70.66 59.51,71.7 61.14,71.7 61.98,72.54 61.98,73.96 62.76,74.75 80.98,74.75 86.61,80.39 86.61,81.41 87,81.79 87.88,81.79 90.56,84.46 90.56,87.05 92.37,88.86 119,88.86 119.53,89.4 122.66,89.4 122.81,89.55 122.81,90.09 122.66,90.24 120.32,90.24 120.17,90.39 120.17,90.7 120.32,90.85 122.86,90.85 123.01,91 123.01,91.31 122.86,91.46 120.32,91.46 120.17,91.61 120.17,91.92 120.32,92.07 122.86,92.07 123.01,92.22 123.01,92.53 122.86,92.68 120.32,92.68 120.17,92.83 120.17,93.14 120.32,93.29 122.86,93.29 123.01,93.44 123.01,95.55 121.54,97.03
LCD_R7: length 121.7
  TOP w0.152: U1.N15 v2(55.67,68.45) ; J1.12 114.1,102.86 117.04,99.92 117.04,99.77 117.55,99.26 120.37,99.26 121.13,98.5 121.13,98.15 120.5,97.51 120.5,96.47 121.03,95.94 121.97,95.94 122.66,95.25 122.66,94.64 122.5,94.49 121.54,94.49
  BOTTOM w0.152: v2(55.67,68.45) 55.67,68.67 57.28,70.28 57.28,71.25 58.7,72.67 60.73,72.67 60.99,72.92 60.99,74.32 62.23,75.56 75.82,75.56 75.98,75.72 75.98,76.17 76.13,76.33 76.43,76.33 76.59,76.17 76.59,75.72 76.74,75.56 77.04,75.56 77.2,75.72 77.2,76.17 77.35,76.33 77.65,76.33 77.81,76.17 77.81,75.72 77.96,75.56 78.26,75.56 78.42,75.72 78.42,76.17 78.57,76.33 78.87,76.33 79.02,76.17 79.02,75.72 79.18,75.56 79.98,75.56 80.14,75.72 80.14,76.27 79.38,77.03 79.38,77.34 79.6,77.57 79.82,77.57 80.49,76.9 80.71,76.9 80.92,77.11 80.92,77.33 80.25,78 80.25,78.22 80.46,78.43 80.68,78.43 81.35,77.76 81.57,77.76 81.78,77.97 81.78,78.19 81.11,78.86 81.11,79.08 81.33,79.29 81.54,79.29 82.22,78.62 82.43,78.62 82.65,78.84 82.65,79.05 81.97,79.73 81.97,79.94 82.19,80.16 82.4,80.16 83.08,79.48 83.29,79.48 83.51,79.7 83.51,79.92 82.84,80.59 82.84,80.8 83.05,81.02 83.27,81.02 83.94,80.35 84.16,80.35 84.37,80.56 84.37,80.78 83.7,81.45 83.7,81.67 83.91,81.88 84.13,81.88 84.8,81.21 85.02,81.21 85.23,81.42 85.23,81.64 84.56,82.31 84.56,82.53 84.78,82.75 84.99,82.75 85.67,82.07 85.88,82.07 86.1,82.29 86.1,82.5 85.42,83.18 85.42,83.39 85.64,83.61 85.86,83.61 86.53,82.93 86.74,82.93 86.96,83.15 86.96,83.37 86.29,84.04 86.29,84.25 91.73,89.7 113.19,89.7 113.61,90.11 113.82,90.11 113.99,89.95 114.2,89.95 114.42,90.16 114.42,90.38 114.25,90.54 114.25,90.76 116.13,92.63 116.76,92.63 117.96,93.83 117.96,95.73 118.11,95.89 121.39,95.89 121.54,95.73 121.54,94.49
LCD_VSYNC: length 122.1
  TOP w0.152: 93.6,97.03 93.6,96.16 93.98,95.78 94.54,95.78 94.69,95.94 94.69,98.76 95.63,99.69 96.44,99.69 97.2,100.46 101.17,100.46 103.61,102.89 J1.33 ; U1.H2 v2(50.87,57.25)
  ART03 w0.114: v1(65.53,80.64) 64.9,81.28 63.92,81.28 61.38,83.82 50.71,83.82 49.57,82.68 44.92,82.68 38.39,76.15 38.39,64.39 39.52,63.27 39.52,61.61 41.27,59.86 41.27,59.18 44.96,55.5 48.77,55.5 49.28,54.99 50.11,54.99 51.31,56.18 51.31,56.81 v2(50.87,57.25)
  BOTTOM w0.152: v1(65.53,80.64) 65.53,81.15 76.53,92.15 78.36,92.15 78.85,92.64 78.85,92.86 78.31,93.39 78.31,93.61 78.53,93.82 78.75,93.82 79.28,93.29 79.5,93.29 79.86,93.65 79.86,95.07 80.14,95.35 81.52,95.35 81.67,95.5 81.67,96.06 81.82,96.22 82.13,96.22 82.28,96.06 82.28,95.5 82.43,95.35 82.74,95.35 82.89,95.5 82.89,96.06 83.04,96.22 83.35,96.22 83.5,96.06 83.5,95.5 83.65,95.35 83.96,95.35 84.11,95.5 84.11,96.06 84.26,96.22 84.57,96.22 84.72,96.06 84.72,95.5 84.87,95.35 85.22,95.35 85.5,95.63 92.2,95.63 93.6,97.03
LED0: length 14.3
  TOP w0.152: D132.1 69.34,54.23 68.33,55.24 63.88,55.24 59.08,60.05 U1.U5
LINKACT2: length 37.1
  TOP w0.254: U3.13 11.09,79.84 10.92,80.01 R1785.1
  TOP w0.305: R1785.1 10.44,80.37 10.16,80.64 10.16,82.25 9.86,82.55 9.4,82.55 4.95,87 4.95,101.09 9.02,105.16 12.34,105.16 J3.11
MP1_VCC: length 15.6
  TOP w0.254: U8.9 87.62,42.03 88.14,42.55 89.03,42.55 90.04,43.56 D112.2 v1(91.06,43.84) ; v1(93.47,36.89) C1790.2 91.86,36.89 R1604.2
  BOTTOM w0.305: v1(91.06,43.84) 91.06,39.31 v1(93.47,36.89)
MS_DWN: length 70.5
  TOP w0.152: U134.4 14.35,51.05 13.82,50.52 10.82,50.52 10.29,51.05 10.29,54.36 11.43,55.5 12.57,55.5 13.08,56.01 13.08,57.4 12.45,58.04 10.54,58.04 9.27,59.31 12.19,62.23 14.15,62.23 14.3,62.38 S3.2 14.3,64.31 13.84,64.77 13.21,64.77 12.73,65.25 C185.1 R1740.2 13.82,66.65 14.22,67.06 31.57,67.06 32.13,66.5 32.13,63.63 34.54,61.21 38.35,61.21 40.51,63.37 41.78,63.37 42.42,64.01 42.42,64.39 43.05,65.02 44.58,65.02 44.8,65.25 46.07,65.25 U1.B11
MS_I2CSCL: length 46
  TOP w0.152: R1755.2 v1(27.91,40.13) 27.91,40.92 27.3,41.53 U134.25
  BOTTOM w0.152: J78.11 21.46,54.74 24.77,54.74 25.53,53.98 28.45,53.98 31.37,51.05 32.77,51.05 33.78,50.04 33.78,49.66 37.16,46.28 37.16,37.8 36.45,37.08 32.13,37.08 29.08,40.13 v1(27.91,40.13)
MS_I2CSDA: length 46.5
  TOP w0.152: U134.26 27.28,44.07 R1756.2 v1(27.91,42.55)
  BOTTOM w0.152: J78.9 19.56,54.1 24.13,54.1 25.4,52.83 28.57,52.83 30.86,50.55 32.64,50.55 33.34,49.85 33.34,49.47 36.7,46.1 36.7,38.86 35.94,38.1 32,38.1 27.91,42.19 v1(27.91,42.55)
MS_RST: length 58
  TOP w0.152: U1.C11 v2(46.87,64.45) ; v1(31.5,66.29) 31.24,66.55 22.61,66.55 22.45,66.4 R1741.2 C1908.1 21.36,65.51 22.81,64.06 S5.2 22.81,63.2 21.46,61.85 17.53,61.85 16.45,60.77 13.27,60.77 11.81,59.31 12.45,58.67 13.08,58.67 13.72,58.04 14.99,58.04 15.62,57.4 15.62,55.75 14.73,54.86 12.32,54.86 11.81,54.36 11.81,52.58
  BOTTOM w0.152: v2(46.87,64.45) 46.87,64.22 47.27,63.82 47.27,63.42 47.09,63.25 40.26,63.25 38.23,65.28 32.51,65.28 v1(31.5,66.29)
MS_RX: length 27.6
  TOP w0.152: 19.43,52.58 19.43,54.23 19.68,54.48 24.23,54.48 27.94,50.77 27.94,50.39 R1752.2 28.42,50.52 28.57,50.67 34.37,50.67 34.52,50.83 34.52,52.1 34.04,52.58 32.89,52.58 32.64,52.83 ; 32.64,52.83 32.38,52.58 30.48,52.58 30.1,52.96 S8.2 ; 32.64,52.83 S8.4
MS_TX: length 22.2
  TOP w0.152: 31.37,53.74 31.37,54.74 31.11,54.99 29.08,54.99 28.83,54.74 S8.1 28.8,53.71 28.8,52.7 28.42,52.32 R1751.2 28.19,51.56 24.77,54.99 17.27,54.99 16.89,54.61 U134.3
Net_2: length 45.3
  TOP w0.152: 48.07,56.85 48.07,55.56 47.35,54.84 47.35,54.05 44.85,51.55 44.85,49.04 43.56,47.75 43.56,47.24 v1(42.8,46.48)
  ART08 w0.114: v1(42.8,46.48) 43.38,47.07 44.25,47.07 44.45,46.86 44.45,42.77 43.15,41.48 43.15,37.72 45.95,34.92 45.95,31.04 47,29.98 47,28.56 50.09,25.48 51.82,25.48 52.93,24.36 52.93,23.39 v1(54.13,22.2)
NRST: length 73.2
  TOP w0.152: v2(53.34,56.13) 53.34,56.38 U1.K1 ; v2(60.83,58.93) 61.09,58.93 65.53,63.37 65.53,73.41 63.75,75.18 59.31,75.18 58.8,75.69 58.8,80.14 57.78,81.15 54.36,81.15 v1(53.66,81.85) ; J6.5 56.49,103.53 57.02,103 58.04,103 59.05,101.98 59.05,95.5 55.63,92.07 S11.2 54.69,90.76 53.82,89.89 R1800.2 C1965.1 v1(53.7,88.8)
  BOTTOM w0.152: v2(53.34,56.13) 53.98,56.13 54.29,56.45 55.05,56.45 56.25,57.65 59.55,57.65 v2(60.83,58.93) ; v1(53.66,81.85) 53.7,81.89 v1(53.7,88.8)
OSC32_IN: length 10.8
  TOP w0.152: U1.C2 46.87,57.25 46.87,56.47 43.89,53.49 42.21,53.49 C433.2 41.17,52.22 40.51,51.56 X4.1
OSC32_OUT: length 9.4
  TOP w0.152: U1.C1 47.27,56.29 44.04,53.06 42.65,53.06 42.27,52.68 C432.2 42.27,52.22 43.01,51.48 X4.2
OSC_IN: length 12.8
  TOP w0.152: U1.J2 51.67,57.25 51.67,56.39 51.05,55.77 51.05,55.12 49.15,53.21 48.51,53.21 48.23,52.93 R84.1 47.62,51.97 47.62,51.03 C355.2 47.62,50.06 47.62,48.71 X3.1
OSC_OUT: length 6.7
  TOP w0.152: U1.J1 52.07,56.13 51.44,55.5 51.44,54.74 49.28,52.58 R84.2 R32.2
PHY_3V3: length 21.5
  TOP w0.254: v1(17.78,74.3) 17.52,74.04 U3.31 ; U3.30 17.02,74.04 v1(16.76,74.3) ; U3.41 v1(20.08,76.34) ; v1(11.68,74.84) U3.23
  TOP w0.305: R1770.1 v1(16.89,68.96) ; v1(30.99,73.53) 30.99,73.89 R1781.2 31.75,73.89 v1(31.75,73.53) 31.75,73.05 C2000.2 30.71,72.67 30.67,72.71 X5.4 ; v1(11.68,83.72) R1784.2 R1786.2 ; R1790.1 v1(11.28,85.19) ; R1791.1 v1(8.13,85.19) ; R1768.2 v1(20.07,68.96) ; R1785.2 v1(8.76,80.01) ; R1773.2 v1(13.84,68.96) ; C1955.2 11.65,74.8 v1(11.68,74.84) ; R1769.2 v1(19.05,68.96)
  BOTTOM w0.305: v1(16.76,74.3) 16.79,74.27 C2024.2 ; C2023.2 17.88,74.19 v1(17.78,74.3) ; C2025.2 19.96,76.23 v1(20.08,76.34)
  vias: v1(10.92,72.9) v1(10.92,71.75) v1(11.94,72.9) v1(11.94,71.75)
PHY_INT: length 83.9
  TOP w0.152: R946.2 v1(18.03,68.96) ; v1(59.82,54.23) 59.69,54.1 59.69,46.86 59.05,46.23 54.79,46.23 51.49,42.93 v1(43.69,42.93) ; U1.T11 v2(58.07,65.25)
  BOTTOM w0.152: v1(59.82,54.23) 62.23,56.64 62.23,63.63 61.01,64.85 58.47,64.85 v2(58.07,65.25) ; v1(43.69,42.93) 43.08,42.93 41.4,44.6 41.4,45.97 40.58,46.8 39.69,46.8 39.17,47.32 39.17,48.97 33.27,54.86 33.27,58.17 31.75,59.69 29.08,59.69 26.8,61.98 26.8,65.66 24.54,67.92 19.08,67.92 v1(18.03,68.96)
PHY_RESET: length 35.7
  TOP w0.152: U1.B12 46.07,66.05 44.49,66.05 44.37,66.17 43.56,66.17 42.04,64.64 42.04,64.24 41.68,63.88 40.39,63.88 38.23,61.72 36.96,61.72 36.58,62.1 36.58,62.61 33.88,65.3 33.88,66.83 32.13,68.58 27.56,68.58 25.37,70.76 R1826.1 22.99,72.8 22.99,75.18 22.33,75.84 U3.40
POWER_OFF: length 87.2
  TOP w0.152: U1.R16 56.47,69.25 56.47,69.85 56.71,70.09 v1(56.71,73.91) ; v1(79.5,14.99) R1554.2 80.26,15.09 Q36.1
  ART08 w0.114: v1(56.71,73.91) 57.39,74.6 61.26,74.6 61.67,75.01 71.3,75.01 78.33,67.97 78.33,51.64 80.59,49.38 80.59,46.63 79.4,45.44 79.4,34.57 79.25,34.42 79.25,30.35 79.4,30.2 79.4,15.09 v1(79.5,14.99)
PWR_INT_N: length 81.3
  TOP w0.152: U1.R15 57.27,68.45 57.27,73.4 v1(57.78,73.91) ; R406.1 v1(76.33,19.08)
  ART08 w0.114: v1(57.78,73.91) 61.44,73.91 62.1,74.57 71.09,74.57 77.85,67.82 77.85,51.38 78.41,50.83 78.41,46.08 78.11,45.77 78.11,43.15 78.87,42.39 78.87,35.46 78.05,34.65 78.05,30.4 78.87,29.59 78.87,21.62 v1(76.33,19.08)
QUADSPI_BK1_IO0: length 16.5
  TOP w0.152: U1.K4 v2(53.27,58.85) ; U77.5 51.94,51.69 51.54,51.28 R1817.2 50.93,50.57 50.77,50.42 v1(50.55,50.42)
  ART03 w0.114: v1(50.55,50.42) 50.55,51.71 50.44,51.82 50.44,52.11 50.33,52.22 49.62,52.22 49.5,52.34 49.5,52.57 49.62,52.68 50.33,52.68 50.44,52.79 50.44,53.02 50.33,53.14 49.62,53.14 49.5,53.25 49.5,53.48 49.62,53.59 50.33,53.59 50.44,53.71 50.44,54.08 52.45,56.08 52.45,57.18 52.87,57.59 52.87,58.45 v2(53.27,58.85)
QUADSPI_BK1_IO1: length 18.3
  TOP w0.152: R1819.2 v1(61.72,49.15) U77.2 ; U1.L4 v2(54.07,58.85)
  ART03 w0.114: v2(54.07,58.85) 54.31,58.85 55.27,57.89 55.27,56.67 55.09,56.49 55.09,55.63 55.38,55.33 55.38,54.5 55.75,54.13 55.75,53.34 58.04,51.05 61.93,51.05 62.31,50.67 62.31,49.73 v1(61.72,49.15)
QUADSPI_BK1_IO2: length 18
  TOP w0.152: U77.3 v1(61.72,50.42) R1820.2 ; U1.K3 v2(53.27,58.05)
  ART03 w0.114: v2(53.27,58.05) 53.67,58.45 54.24,58.45 54.47,58.22 54.47,56.72 54.1,56.35 54.1,55.84 54.74,55.21 54.74,52.32 56.64,50.42 v1(61.72,50.42)
QUADSPI_BK1_IO3: length 17.4
  TOP w0.152: R1818.2 51.41,49.56 v1(51.69,49.28) 51.82,49.15 U77.7 ; U1.K2 v2(53.27,57.25)
  ART03 w0.114: v1(51.69,49.28) 51.13,49.83 51.13,50.83 51.3,50.99 52.21,50.99 52.32,51.1 52.32,51.58 52.21,51.7 51.14,51.7 51.03,51.81 51.03,52.04 51.14,52.15 52.21,52.15 52.32,52.27 52.32,52.72 52.21,52.83 52.07,52.83 51.94,52.96 51.94,53.21 52.45,53.72 52.45,53.98 52.2,54.23 52.07,54.23 51.45,53.61 51.29,53.61 51.05,53.85 51.05,54.08 52.83,55.85 52.83,56.81 v2(53.27,57.25)
QUADSPI_BK1_NCS: length 33.1
  TOP w0.152: U77.1 v1(61.72,47.88) R898.2 ; U1.G15 v2(50.07,68.45)
  ART06 w0.099: v1(61.72,47.88) 57.94,47.88 51.84,53.98 50.16,53.98 48.06,56.08 48.06,67.11 48.21,67.26 48.89,67.26 v2(50.07,68.45)
QUADSPI_CLK: length 17.1
  TOP w0.152: U77.6 v1(51.69,50.42) ; U1.L3 v2(54.07,58.05)
  ART03 w0.114: v2(54.07,58.05) 53.67,57.65 53.67,56.77 53.72,56.72 53.72,55.88 53.52,55.68 53.52,55.5 52.96,54.94 52.96,49.81 53.07,49.7 53.28,49.7 53.39,49.58 53.39,49.36 53.28,49.24 53.07,49.24 52.96,49.13 52.96,48.9 53.07,48.78 53.28,48.78 53.39,48.67 53.39,48.44 53.28,48.33 53.07,48.33 52.96,48.21 52.96,48.01 52.81,47.85 52.35,47.85 52.24,47.97 52.24,50.3 52.13,50.42 v1(51.69,50.42)
RE_0: length 13.4
  TOP w0.305: J75.1 15.24,12.37 15.37,12.5 15.37,16.89 14.86,17.4 14.35,17.4 14.1,17.65 J76.3 14.1,20.57 14.35,20.83 U134.16
RE_1: length 16.8
  TOP w0.305: U134.14 6.63,28.83 6.22,28.42 6.22,23.62 10.29,19.56 10.29,17.4 J76.8
RX+: length 20
  TOP w0.13: v2(19.15,85.09) 18.94,84.87 18.94,82.21 19.02,82.12 U3.3
  BOTTOM w0.13: v2(19.15,85.09) 18.94,85.31 18.94,85.73 18.61,86.05 16.88,86.05 15.87,85.04 14.64,85.04 14.51,85.17 14.51,85.53 R1795.2 14.51,86.17 14.51,86.65 15.28,87.42 15.47,87.42 15.5,87.39 15.68,87.39 15.87,87.57 15.87,87.75 15.83,87.79 15.83,87.97 17.14,89.28 17.14,90.55 17.91,91.31 18.2,91.31 J3.3
RX-: length 20
  TOP w0.13: v2(18.39,85.09) 18.61,84.87 18.61,82.21 18.52,82.12 U3.4
  BOTTOM w0.13: v2(18.39,85.09) 18.61,85.31 18.61,85.6 18.48,85.72 17.02,85.72 16,84.71 14.51,84.71 14.19,85.03 14.19,85.53 R1796.2 14.19,86.17 14.19,86.79 16.82,89.42 16.82,90.69 17.1,90.97 17.1,91.35 16.89,91.57 16.13,91.57 15.75,91.19 J3.6
SDIO0_CARD_DETECT: length 40.3
  TOP w0.152: J8.9 43.84,92.43 45.06,91.21 R118.2 45.06,84.94 44.7,84.58 42.29,84.58 41.63,83.92 41.63,76.17 v1(41.4,75.95) ; U1.C9 v2(46.87,63.65)
  BOTTOM w0.152: v1(41.4,75.95) 39.62,74.17 39.62,65.91 41.05,64.49 46.03,64.49 v2(46.87,63.65)
SDIO0_CARD_POWER_EN: length 48.4
  TOP w0.152: U1.U3 v2(58.87,58.05) ; R119.2 R116.1 44.42,78.92 45.62,77.72 54.74,77.72 56.52,79.5 57.91,79.5 58.17,79.25 58.17,75.69 59.31,74.55 63.75,74.55 64.95,73.36 64.95,63.55 61.34,59.94 v2(60.83,59.94)
  BOTTOM w0.152: v2(60.83,59.94) 58.94,58.05 v2(58.87,58.05)
SDIO0_CCLK_OUT: length 29.9
  TOP w0.152: R281.1 39.37,69.06 39.37,71.12 39.81,71.56 39.81,86.93 v1(40.39,87.5) ; J8.5 v1(39.58,91.95)
  BOTTOM w0.152: v1(39.58,91.95) 39.58,91.25 39.73,91.1 40.44,91.1 40.59,90.94 40.59,90.64 40.44,90.49 39.73,90.49 39.58,90.33 39.58,90.03 39.73,89.88 40.44,89.88 40.59,89.72 40.59,89.42 40.44,89.27 39.73,89.27 39.58,89.11 39.58,88.31 v1(40.39,87.5)
SDIO0_CCMD: length 28.9
  TOP w0.152: J8.3 v1(37.38,92.11) ; R1221.1 38.86,68.43 38.86,71.75 39.24,72.14 39.24,84.68 39.09,84.83 39.01,84.83 38.86,84.99 38.86,85.29 39.01,85.44 39.09,85.44 39.24,85.6 39.24,85.9 39.09,86.05 39.01,86.05 38.86,86.2 38.86,86.51 39.01,86.66 39.09,86.66 39.24,86.81 39.24,87.25 v1(38.99,87.5)
  BOTTOM w0.152: v1(37.38,92.11) 38.99,90.5 v1(38.99,87.5)
SDIO0_CDATA0: length 27.7
  TOP w0.152: R1222.1 39.88,69.7 39.88,70.87 40.39,71.37 40.39,85.52 41.1,86.23 v1(41.66,86.23) ; J8.7 v1(41.78,91.95)
  BOTTOM w0.152: v1(41.78,91.95) 41.78,91.21 41.62,91.05 41.35,91.05 41.2,90.9 41.2,90.6 41.35,90.44 41.62,90.44 41.78,90.29 41.78,89.99 41.62,89.83 41.35,89.83 41.2,89.68 41.2,89.38 41.35,89.23 41.62,89.23 41.78,89.07 41.78,88.51 41.02,87.76 41.02,86.87 v1(41.66,86.23)
SDIO0_CDATA1: length 27.4
  TOP w0.152: J8.8 v1(42.88,91.95) ; R1223.1 40.49,70.74 40.89,71.15 40.89,71.57 41.05,71.72 41.38,71.72 41.53,71.87 41.53,72.18 41.38,72.33 41.05,72.33 40.89,72.48 40.89,72.79 41.05,72.94 41.38,72.94 41.53,73.09 41.53,73.4 41.38,73.55 41.05,73.55 40.89,73.7 40.89,74.01 41.05,74.16 41.38,74.16 41.53,74.31 41.53,74.62 41.38,74.77 41.05,74.77 40.87,74.95 40.87,76.3 41.14,76.57 41.14,84.72 42.42,86 42.42,86.74 v1(41.66,87.5)
  BOTTOM w0.152: v1(42.88,91.95) 42.88,88.72 v1(41.66,87.5)
SDIO0_CDATA2: length 34
  TOP w0.152: J8.1 v1(35.18,92.08) ; v1(37.72,87.5) 37.15,86.93 37.15,86.5 37,86.34 36.86,86.34 36.7,86.19 36.7,85.89 36.86,85.73 37,85.73 37.15,85.58 37.15,85.28 37,85.12 36.86,85.12 36.7,84.97 36.7,84.67 36.86,84.51 37,84.51 37.15,84.36 37.15,84.06 37,83.9 36.86,83.9 36.7,83.75 36.7,83.45 36.86,83.3 37,83.3 37.15,83.14 37.15,81.6 38.35,80.39 38.35,73.41 37.85,72.9 37.85,67.16 R1224.1
  BOTTOM w0.152: v1(37.72,87.5) 37.72,90.55 36.2,92.08 v1(35.18,92.08)
SDIO0_CDATA3: length 33.7
  TOP w0.152: v1(37.72,86.23) 37.72,85.22 38.73,84.2 38.73,83.79 38.58,83.64 38.25,83.64 38.1,83.49 38.1,83.18 38.25,83.03 38.58,83.03 38.73,82.88 38.73,82.57 38.58,82.42 38.25,82.42 38.1,82.27 38.1,81.97 38.25,81.81 38.58,81.81 38.73,81.66 38.73,72.52 38.35,72.14 38.35,67.79 R1225.1 ; v1(35.18,90.81) 36.28,91.9 J8.2
  BOTTOM w0.152: v1(35.18,90.81) 34.54,90.17 34.54,88.14 36.45,86.23 v1(37.72,86.23)
SPEEDLED2: length 34.3
  TOP w0.305: J3.10 16.67,103.92 15.24,102.49 9.65,102.49 6.48,99.31 6.48,90.04 9.78,86.74 9.78,84.07 Q18.3
TP_I2C1_SCL: length 19.5
  TOP w0.152: 88.52,97.03 88.52,99.57 88.65,99.69 R1812.1 89.13,101.19 90.35,102.41 96.22,102.41 96.42,102.21 R1760.2 100.84,101.85 101.61,102.62 J1.37
TP_I2C1_SDA: length 25.1
  TOP w0.152: 88.52,94.49 87.38,95.63 R1811.1 87.86,101.19 88.01,101.35 88.01,103.25 88.46,103.7 96.2,103.7 96.42,103.48 R1759.2 97.03,103 97.79,102.23 100.58,102.23 101.1,102.76 J1.38
TP_INT: length 73.5
  TOP w0.152: v1(57.28,78.87) 57.28,75.95 60.58,72.64 60.58,68.55 U1.U13 ; J2.39 85.98,98.93 86.13,99.09 R1828.2 R1830.2 86.13,103.15 87.12,104.14 96.77,104.14 98.3,102.62 100.33,102.62 100.61,102.89 J1.39
  BOTTOM w0.152: J2.39 81.08,97.03 76.71,92.66 76.4,92.66 64.95,81.2 64.16,81.2 62.08,79.12 57.53,79.12 v1(57.28,78.87)
TP_RESET: length 98.1
  TOP w0.152: U1.P3 56.47,58.05 57.12,58.05 57.27,57.89 57.27,53.73 v1(57.4,53.59) ; J2.40 84.23,96.24 C1980.1 R1829.1 84.23,102.9 85.98,104.65 97.41,104.65 99.06,103 99.95,103 100.1,103.15 J1.40
  ART03 w0.114: v1(57.4,53.59) 58.8,52.2 62.23,52.2 63.25,51.18 69.09,51.18 69.22,51.31 73.15,51.31 74.42,52.58 74.42,55.75 76.07,57.4 76.07,84.58 J2.40
TX+: length 16.5
  TOP w0.13: U3.7 17.02,82.16 16.94,82.25 16.94,83.22 v2(17.15,83.44)
  BOTTOM w0.13: J3.1 21.59,91.67 21.65,91.49 21.86,91.39 22.3,90.95 22.3,87.93 21.25,86.88 21.25,86.17 R1793.2 21.25,85.53 21.25,84.69 20.55,84 17.1,84 16.94,83.84 16.94,83.66 v2(17.15,83.44)
TX-: length 16.5
  TOP w0.13: v2(16.39,83.44) 16.61,83.22 16.61,82.27 16.52,82.18 U3.8
  BOTTOM w0.13: J3.2 21.33,91.14 21.51,91.2 21.67,91.12 21.97,90.82 21.97,88.06 21.64,87.73 21.46,87.73 21.41,87.78 21.23,87.78 21.04,87.59 21.04,87.41 21.09,87.37 21.09,87.18 20.92,87.01 20.92,86.17 R1794.2 20.92,85.53 20.92,84.83 20.42,84.33 16.96,84.33 16.61,83.98 16.61,83.66 v2(16.39,83.44)
UART1_RX: length 71.7
  TOP w0.152: U1.C5 46.87,60.45 45.46,60.45 45.21,60.2 44.45,60.2 42.62,58.37 35.13,58.37 34.42,57.66 34.42,53.26 34.98,52.7 34.98,47.87 36.96,45.89 36.96,34.85 33.4,31.3 33.4,13.72 31.24,11.56 R1626.2 32.36,8.92 32.64,8.64 D76.1 32.64,6.99 33.06,6.56 J63.3
UART1_TX: length 68.2
  TOP w0.152: U1.B5 46.07,59.65 44.79,59.65 43.08,57.94 35.33,57.94 34.92,57.53 34.92,53.47 35.43,52.96 35.43,48.01 37.47,45.97 37.47,34.8 33.78,31.11 33.78,16.13 34.67,15.24 D76.2 34.67,6.99 34.31,6.63 J63.2
UART3_RX: length 58.5
  TOP w0.152: U1.P12 v2(56.47,66.05) ; S8.8 28.19,61.96 28.19,62.99 28.55,63.35 R1865.2 28.96,62.61 v1(28.83,62.48)
  BOTTOM w0.152: v1(28.83,62.48) 29.84,61.47 32.13,61.47 35.67,57.92 35.67,57.16 39.75,53.09 44.37,53.09 45.38,52.07 49.53,52.07 50.67,50.93 55.75,50.93 61.8,56.97 61.8,63.3 61.05,64.05 57.89,64.05 57.67,64.26 57.67,65.42 57.44,65.65 56.87,65.65 v2(56.47,66.05)
UART3_TX: length 52.9
  TOP w0.152: S8.7 v1(30.1,62.48) ; U1.P11 v2(56.47,65.25)
  BOTTOM w0.152: v2(56.47,65.25) 56.87,64.85 56.87,64.24 57.06,64.05 57.45,64.05 57.67,63.83 57.67,63.4 57.82,63.25 61.09,63.25 61.42,62.92 61.42,57.23 58.55,54.36 57.28,54.36 56.77,53.85 56.77,52.96 55.12,51.31 50.91,51.31 49.64,52.58 45.42,52.58 44.53,53.47 41.66,53.47 38.48,56.64 37.72,56.64 31.88,62.48 v1(30.1,62.48)
UART4_RX: length 43.2
  TOP w0.152: v1(45.91,74.99) 45.91,74.36 48.81,71.46 48.81,69.7 U1.E17 ; v1(49.78,80.14) 52.96,83.31 56.64,83.31 56.87,83.54 56.87,91.8 62.48,97.41 62.48,101.75 R1815.2
  BOTTOM w0.152: v1(49.78,80.14) 49.21,79.57 49.21,78.3 v1(45.91,74.99)
UART4_TX: length 44.2
  TOP w0.152: U1.E16 48.47,69.25 48.47,70.12 48.01,70.58 48.01,71.37 45.34,74.04 v1(45.09,74.04) ; R1816.2 63.09,97.51 57.23,91.64 57.23,83.36 56.8,82.93 53.34,82.93 49.78,79.38 v1(49.78,78.99)
  BOTTOM w0.152: v1(45.09,74.04) 45.92,74.04 49.78,77.9 v1(49.78,78.99)
USB3_DM: length 81.1
  TOP w0.155: v2(46.9,7.16) 47.09,6.97 47.09,6.7 46.99,6.61 J73.B7 ; U1.U15 v2(58.87,68.45) ; v2(47.6,9.27) 47.41,9.08 47.41,8.47 47.74,8.14 J73.A7
  BOTTOM w0.155: v2(58.87,68.45) 58.73,68.31 58.73,68.09 58.9,67.92 60.73,67.92 63.63,65.02 63.63,56.52 58.42,51.31 58.42,43.1 55.76,40.44 54.87,40.44 54.1,39.67 54.1,34.54 54.64,34.01 54.64,30.38 52.71,28.45 52.03,28.45 51.69,28.11 51.69,26.92 49.28,24.51 49.28,13.97 49.43,13.82 49.53,13.82 49.68,13.66 49.68,13.35 49.53,13.2 49.43,13.2 49.28,13.04 49.28,12.45 48.34,11.51 48.34,11.29 48.46,11.17 48.46,10.95 48.24,10.73 48.02,10.73 47.9,10.85 47.68,10.85 47.37,10.54 47.37,10.2 D108.1 47.37,9.62 47.37,9.5 v2(47.6,9.27) 47.4,9.07 47.4,8.53 47.02,8.16 46.21,8.16 45.52,7.46 45.52,6.81 45.85,6.48 46.91,6.48 47.09,6.66 47.09,6.97 v2(46.9,7.16)
USB3_DP: length 81.1
  TOP w0.155: v2(47.61,7.16) 47.41,6.97 47.41,6.69 47.49,6.61 J73.B6 ; U1.T15 v2(58.07,68.45) ; v2(46.89,9.27) 47.08,9.08 47.08,8.47 46.74,8.14 J73.A6
  BOTTOM w0.155: v2(58.07,68.45) 58.4,68.11 58.4,67.95 58.77,67.59 60.6,67.59 63.3,64.89 63.3,56.65 58.09,51.44 58.09,43.23 55.63,40.77 54.74,40.77 53.77,39.8 53.77,34.41 54.31,33.87 54.31,30.51 52.57,28.78 51.89,28.78 51.36,28.25 51.36,27.06 48.95,24.65 48.95,12.58 47.04,10.68 47.04,10.12 D109.1 47.04,9.69 47.04,9.43 v2(46.89,9.27) 47.07,9.09 47.07,8.67 46.88,8.48 46.08,8.48 45.19,7.6 45.19,6.67 45.71,6.15 47.04,6.15 47.41,6.52 47.41,6.97 v2(47.61,7.16)
USB_OTG_ID: length 4.2
  TOP w0.152: U1.T14 v2(58.07,67.65)
  BOTTOM w0.152: v2(58.07,67.65) 57.67,68.05 57.67,68.68 57.83,68.85 59.42,68.85 59.56,68.99 R1859.2
WE_0: length 16.6
  TOP w0.305: J75.5 17.78,14.99 J76.2 16,16.76 16,17.14 15.37,17.78 15.37,19.68 16.89,21.21 U134.17
WE_1: length 16.6
  TOP w0.305: U134.13 6.48,31.37 5.33,30.23 5.33,22.35 J76.7
N06481: length 26.9
  TOP w0.254: R1386.1 49.26,31.62 49,31.88 U117.18
  TOP w0.305: R1386.1 51.08,31.09 51.44,30.73 51.44,26.29 50.42,25.27 50.42,24.51 49.28,23.37 49.28,19.3 48.83,18.86 C1509.1 47.28,18.86 R1382.1 46.86,16.76 46.35,16.26 41.27,16.26
N07169: length 25.3
  TOP w0.254: R1383.2 v1(48.51,40.64)
  TOP w0.305: v1(50.42,28.07) 50.42,26.04 49.91,25.53 49.91,24.89 49.5,24.49 R1381.2 48.77,23.98 48.77,23.75 48.2,23.18 C1510.2 48.2,20.32 C1509.2 47.03,20.26 R1382.2
  BOTTOM w0.254: v1(48.51,40.64) 48.51,37.59 51.44,34.67 51.44,29.08 v1(50.42,28.07)
N07181: length 16
  TOP w0.254: v1(53.72,31.75) 53.59,31.62 R1386.2 ; R1387.2 TS1.1
  BOTTOM w0.254: v1(53.72,31.75) 53.72,33.4 51.63,35.5 51.63,36.64 49.94,38.33 49.94,41.12 49.66,41.4 48.01,41.4 TS1.1
N07533: length 2.8
  TOP w0.254: R1387.1 47.5,38.35 47.5,38.35 U117.4
N07661: length 3
  TOP w0.254: R1383.1 48.51,38.96 48.51,38.35 48,37.84 U117.3
N07823: length 2.8
  TOP w0.152: U117.12 45.49,32.91 44.2,31.62 R1389.1
N07951: length 2.3
  TOP w0.152: U117.13 46.5,32.02 46.1,31.62 45.36,31.62 45.21,31.47 R1388.1
N08069: length 1.8
  TOP w0.152: R1390.1 44.73,36.17 45.49,35.41 U117.7
N08149: length 1.5
  TOP w0.152: R1501.2 44.83,35.18 45.1,34.91 U117.8
N08736: length 1.6
  TOP w0.152: Q2.3 R25.2
N08740: length 2.1
  TOP w0.152: R119.1 42.65,82.14 42.93,82.42 Q2.1
N08748: length 3.8
  TOP w0.152: R25.1 C75.2 R135.2 42.32,88.52 41.53,88.52
N14544: length 2.5
  TOP w0.203: U133.4 v2(58.95,26.67)
  BOTTOM w0.508: C1641.2 59.2,26.92 v2(58.95,26.67)
N14548: length 4.6
  BOTTOM w0.508: C1641.1 61.72,26.92 v1(63.75,24.89) v1(64.52,24.89)
  vias: v1(63.75,24.13) v1(64.52,24.13) v2(58.67,24.49) v2(58.67,23.88) v2(59.31,24.49) v2(59.31,23.88)
N14620: length 1.6
  TOP w0.152: R1448.2 87.63,7.67 U128.6
N14770: length 2.1
  TOP w0.152: R1450.2 86.33,11.18 86.98,11.18 87.13,11.02 U128.4
N14904: length 2.1
  TOP w0.152: U128.5 87.13,7.26 86.98,7.11 86.21,7.11 R1449.2
N14944: length 7.1
  TOP w0.254: U128.8 88.63,7.5 88.77,7.37 89.03,7.37 89.15,7.49
  TOP w0.305: R1446.1 91.82,8.46 91.52,8.76 89.79,8.76 89.53,8.51 89.53,7.87 89.15,7.49
  vias: v1(90.17,4.45) v1(90.17,3.17) v1(91.44,4.45) v1(91.44,3.17) v1(92.71,4.45) v1(92.71,3.17) v1(93.98,5.71) v1(93.98,4.45) v1(93.98,3.17) v1(95.25,5.71) v1(95.25,4.45) v1(95.25,3.17)
N15026: length 5.2
  BOTTOM w0.508: v1(64.52,22.35) v1(63.75,22.35) 63.25,21.84 60.83,21.84 60.33,21.34 C1642.1
  vias: v1(63.75,23.11) v1(64.52,23.11) v2(58.67,22.81) v2(58.67,22.2) v2(59.31,22.81) v2(59.31,22.2)
N15146: length 2.2
  TOP w0.203: v2(58.04,22.23) 58.15,22.12 U133.19
  BOTTOM w0.508: v2(58.04,22.23) 58.04,21.95 58.65,21.34 C1642.2
N15862: length 3.8
  TOP w0.203: U133.18 57.75,19.9 57.52,19.67
  TOP w0.305: R1852.1 56.16,18.69 56.77,19.3 57.15,19.3 57.52,19.67
N16110: length 4.7
  TOP w0.203: U133.24 60.15,21.01 v1(60.58,20.57)
  BOTTOM w0.305: C1653.1 58.42,20.07 58.55,20.19 60.2,20.19 v1(60.58,20.57)
N16190: length 6.1
  TOP w0.203: 56.98,20.7 57.35,21.07 U133.17
  TOP w0.305: R1484.1 54.61,19.18 55.85,20.42 v1(55.85,20.7) 56.98,20.7
  BOTTOM w0.305: v1(55.85,20.7) 55.85,21.29 R1483.2
N16266: length 1.7
  TOP w0.203: v2(58.42,20.7) 58.55,20.83 U133.20
  BOTTOM w0.305: R1481.1 58.06,20.7 v2(58.42,20.7)
N17136: length 4.8
  TOP w0.152: U1.G17 49.43,70.69 R522.2
N26661: length 4.1
  TOP w0.254: U8.15 87.12,39.88 U8.3 87.12,37.47 ; R85.1 89.03,33.27 88.65,32.89
  vias: v1(87.88,36.2) v1(87.88,34.92) v1(87.88,33.66) v1(87.88,32.38)
N27346: length 2.1
  TOP w0.305: R1611.1 63.5,32.77
N29886: length 2.2
  TOP w0.305: R1706.2 72.03,21.49 72.26,21.72 Q35.4
N29984: length 1.1
  TOP w0.305: R1705.2 C1880.2
N30034: length 2.9
  TOP w0.305: R1468.1 72.92,19.08 73.51,19.66 R1706.1 R1705.1
N30108: length 4.3
  TOP w0.152: U37.3 72.71,16 C1879.1 72.33,17.49 R1469.2 72.11,17.7 R1468.2
N30120: length 1.1
  TOP w0.254: 73.03,15.37 73.16,15.5 U37.4
